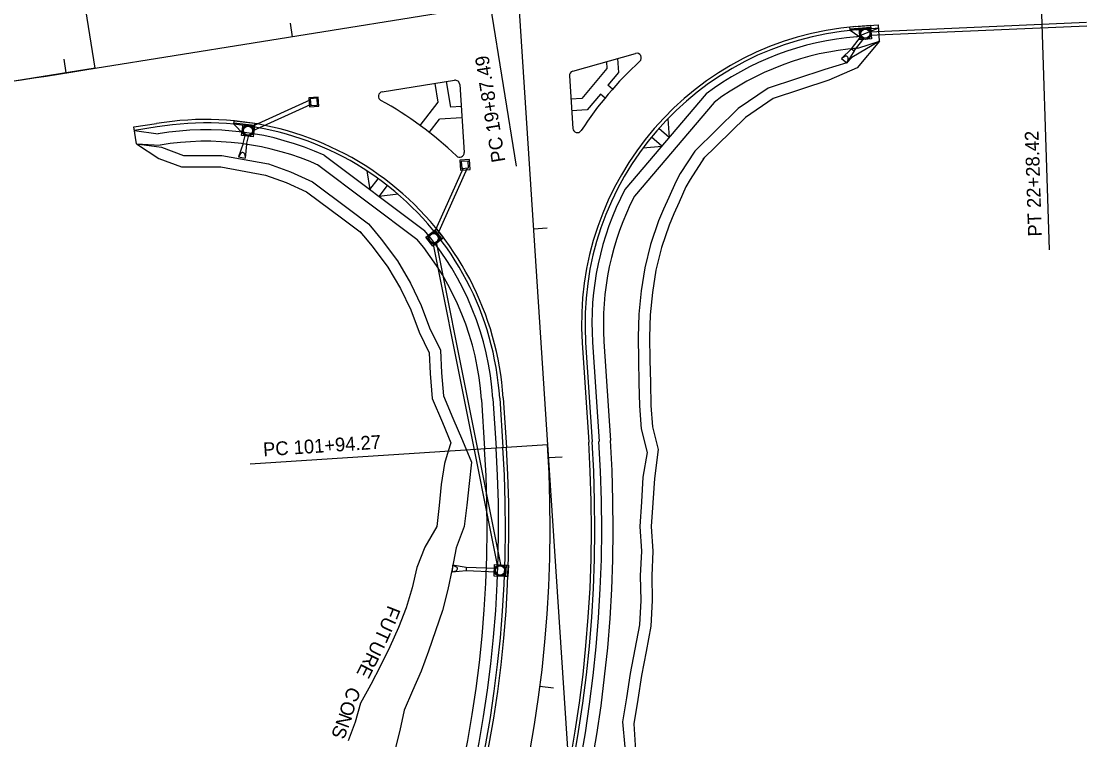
# Model space of a CAD drawing. Extents: x 979959 to 994833, y 1835619 to 1845316.
# Drawn here: x 982435.7 to 982900.6, y 1842333.5 to 1842647 of the extents above; entities that cross this region are included whole.
import ezdxf

# ---------------------------------------------------------------- set-up
doc = ezdxf.new("R2010")
doc.units = 0
for name, color, linetype in [('Future 5 Lane Construction Limits', 7, 'Continuous'), ('R_Drainage', 7, 'Continuous'), ('R_Horz Alg', 7, 'Continuous'), ('R_Horz Alg Annot', 7, 'Continuous'), ('R_Horz Alg Annot_Side Road', 7, 'Continuous'), ('R_Horz Alg Stationing', 7, 'Continuous'), ('R_Horz Alg Stationing_Side Road', 7, 'Continuous'), ('R_Proposed Const Limits', 7, 'Continuous'), ('R_Proposed Road', 7, 'Continuous')]:
    doc.layers.add(name, color=color, linetype=linetype)

msp = doc.modelspace()

# ---------------------------------------------------------------- linework, layer by layer
at = {"layer": 'Future 5 Lane Construction Limits'}
for points in [[(982810.26, 1842638.37), (982800.43, 1842626.73), (982788.12, 1842621.27), (982763.82, 1842613.33), (982751.67, 1842605.09), (982733.13, 1842586.84)], [(982485.98, 1842593.61), (982495.65, 1842587.2), (982505.6, 1842583.46), (982522.74, 1842583.5), (982542.28, 1842579.93), (982551.28, 1842576.73), (982560.22, 1842572.61), (982575.97, 1842560.88), (982584.11, 1842554.66)], [(982733.83, 1842587.7), (982727.56, 1842577.95), (982725.75, 1842574.77), (982722.78, 1842568.13), (982720.46, 1842563.03), (982718.41, 1842558.12), (982715.13, 1842548.23), (982712.66, 1842538.45), (982711.15, 1842528.69), (982710.17, 1842518.91), (982709.88, 1842509.15), (982710.03, 1842499.26), (982710.22, 1842489.28), (982710.47, 1842479.41), (982711.14, 1842469.98), (982713.61, 1842460.1)], [(982583.44, 1842555.27), (982585.09, 1842553.46), (982588.84, 1842548.91), (982595.61, 1842539.65), (982601.13, 1842530.4), (982605.61, 1842521.09), (982609.29, 1842511.28), (982613.73, 1842502.31), (982614.05, 1842493.26), (982614.99, 1842482.38), (982619.43, 1842471.89), (982623.2, 1842463.11)], [(982623.2, 1842463.11), (982622.02, 1842459.42), (982620.34, 1842454.04), (982618.98, 1842444.82), (982618.06, 1842435.67), (982616.99, 1842426.55), (982611.78, 1842417.56), (982608.24, 1842408.68), (982606.24, 1842399.84), (982603.68, 1842391.1), (982600.32, 1842382.5), (982596.45, 1842374.05), (982592.4, 1842365.73), (982588.19, 1842357.54), (982587.38, 1842356.05), (982583.77, 1842349.5), (982581.39, 1842341.2), (982578.38, 1842333.05)], [(982713.61, 1842460.1), (982711.94, 1842447.46), (982711.28, 1842436.93), (982710.57, 1842426.53), (982711.31, 1842415.85), (982710.78, 1842405), (982710.98, 1842394.25), (982710.44, 1842383), (982708.35, 1842372.06), (982706.38, 1842361.59), (982704.77, 1842351.04), (982702.96, 1842340.45)], [(982702.96, 1842340.45), (982704.27, 1842319.44), (982705.92, 1842307.91), (982706.96, 1842296.36), (982707.4, 1842284.83), (982707.25, 1842273.14), (982704.91, 1842261.25), (982696.82, 1842251.43), (982690.14, 1842243.07), (982689.97, 1842232.63)]]:
    msp.add_lwpolyline(points, dxfattribs=at)
at = {"layer": 'R_Drainage'}
for p, q in [((982806.31, 1842644.32), (982797.34, 1842643.65)), ((982805.82, 1842642.47), (982900.54, 1842646.59)), ((982805.89, 1842640.97), (982900.6, 1842645.09)), ((982797.38, 1842643.16), (982802.59, 1842639.58)), ((982797.93, 1842635.07), (982802.27, 1842640.64)), ((982799.12, 1842634.15), (982803.46, 1842639.72)), ((982797.93, 1842635.07), (982793.6, 1842630.74)), ((982797.93, 1842635.07), (982799.12, 1842634.15)), ((982806.68, 1842639.33), (982801.7, 1842638.96)), ((982795.02, 1842631.64), (982793.6, 1842630.74)), ((982793.6, 1842630.74), (982795.97, 1842628.89)), ((982799.12, 1842634.15), (982795.97, 1842628.89)), ((982796.51, 1842630.48), (982795.97, 1842628.89)), ((982535.87, 1842600.89), (982561.81, 1842612.69)), ((982536.63, 1842599.23), (982561.94, 1842610.73)), ((982537.42, 1842601.5), (982528.48, 1842602.6)), ((982528.42, 1842602.1), (982532.84, 1842597.58)), ((982532.49, 1842593.64), (982530.5, 1842587.84)), ((982536.81, 1842596.54), (982531.84, 1842597.15)), ((982532.49, 1842593.64), (982533.96, 1842593.33)), ((982532.5, 1842593.66), (982533.47, 1842597.7)), ((982533.96, 1842593.33), (982533.44, 1842587.22)), ((982533.96, 1842593.31), (982534.93, 1842597.35)), ((982531.38, 1842589.27), (982530.5, 1842587.84)), ((982533.22, 1842588.88), (982533.44, 1842587.22)), ((982530.5, 1842587.84), (982533.44, 1842587.22)), ((982628.55, 1842582.87), (982615.76, 1842554.35)), ((982628.55, 1842582.87), (982615.76, 1842554.35)), ((982630.24, 1842582.98), (982617.13, 1842553.74)), ((982630.24, 1842582.98), (982617.13, 1842553.74)), ((982615.24, 1842548.85), (982612.18, 1842552.8)), ((982615.32, 1842550.39), (982643.54, 1842409.01)), ((982615.32, 1842550.39), (982643.54, 1842409.01)), ((982616.79, 1842550.68), (982645.01, 1842409.3)), ((982616.79, 1842550.68), (982645.01, 1842409.3)), ((982623.81, 1842409.61), (982623.7, 1842406.61)), ((982629.86, 1842408.63), (982623.81, 1842409.61)), ((982625.37, 1842408.99), (982623.81, 1842409.61)), ((982629.86, 1842408.63), (982629.81, 1842407.14)), ((982642.81, 1842408.16), (982629.86, 1842408.63)), ((982642.81, 1842408.16), (982629.86, 1842408.63)), ((982642.05, 1842404.93), (982642.23, 1842409.93)), ((982629.81, 1842407.14), (982623.7, 1842406.61)), ((982625.3, 1842407.1), (982623.7, 1842406.61)), ((982642.76, 1842406.66), (982629.81, 1842407.14)), ((982642.76, 1842406.66), (982629.81, 1842407.14))]:
    msp.add_line(p, q, dxfattribs=at)
for points in [[(982806.35, 1842643.82), (982797.38, 1842643.16), (982797.26, 1842644.65), (982806.24, 1842645.32)], [(982806.68, 1842639.33), (982801.7, 1842638.96), (982801.33, 1842643.95), (982806.31, 1842644.32)], [(982565.24, 1842613.94), (982561.24, 1842613.68), (982561.5, 1842609.68), (982565.5, 1842609.94)], [(982564.77, 1842613.4), (982561.78, 1842613.21), (982561.97, 1842610.22), (982564.96, 1842610.41)], [(982537.36, 1842601), (982528.42, 1842602.1), (982528.61, 1842603.59), (982537.54, 1842602.49)], [(982536.81, 1842596.54), (982531.84, 1842597.15), (982532.45, 1842602.11), (982537.42, 1842601.5)], [(982626.99, 1842586.44), (982627.28, 1842582.12), (982631.6, 1842582.4), (982631.32, 1842586.73)], [(982627.7, 1842585.82), (982627.9, 1842582.83), (982630.89, 1842583.02), (982630.7, 1842586.02)], [(982618.8, 1842551.6), (982615.74, 1842555.56), (982616.93, 1842556.48), (982619.99, 1842552.52)], [(982615.24, 1842548.85), (982612.18, 1842552.8), (982616.13, 1842555.86), (982619.2, 1842551.91)], [(982642.05, 1842404.93), (982642.23, 1842409.93), (982647.23, 1842409.74), (982647.04, 1842404.75)], [(982646.54, 1842404.77), (982646.73, 1842409.76), (982648.23, 1842409.71), (982648.04, 1842404.71)]]:
    msp.add_lwpolyline(points, close=True, dxfattribs=at)
for centre, radius in [((982804.01, 1842641.64), 2.5), ((982804.01, 1842641.64), 2.5), ((982804.01, 1842641.64), 2), ((982804.01, 1842641.64), 2), ((982534.63, 1842599.32), 2.5), ((982534.63, 1842599.32), 2.5), ((982534.63, 1842599.32), 2), ((982534.63, 1842599.32), 2), ((982615.69, 1842552.36), 2.5), ((982615.69, 1842552.36), 2.5), ((982615.69, 1842552.36), 2), ((982615.69, 1842552.36), 2), ((982644.64, 1842407.34), 2.5), ((982644.64, 1842407.34), 2.5), ((982644.64, 1842407.34), 2), ((982644.64, 1842407.34), 2)]:
    msp.add_circle(centre, radius, dxfattribs=at)
for centre, start, end in [((982795.56, 1842630.79), 341.4196, 122.7056), ((982532.23, 1842588.75), 7.3963, 148.6823), ((982625.01, 1842408.06), 287.2412, 68.5271)]:
    msp.add_arc(centre, 1, start, end, dxfattribs=at)
at = {"layer": 'R_Horz Alg'}
for p, q in [((982467.97, 1842626.52), (982640.32, 1842654.16)), ((982652.68, 1842656.1), (982665.33, 1842462.24))]:
    msp.add_line(p, q, dxfattribs=at)
for centre, radius, start, end in [((981863.15, 1846398.05), 3819.72, 276.50701, 279.11059), ((982120.82, 1842426.69), 545.67, 283.2783, 3.7353)]:
    msp.add_arc(centre, radius, start, end, dxfattribs=at)
at = {"layer": 'R_Horz Alg Annot'}
msp.add_lwpolyline([(982665.33, 1842462.24), (982535.61, 1842453.77)], dxfattribs=at)
at = {"layer": 'R_Horz Alg Annot_Side Road'}
for p, q in [((982467.97, 1842626.52), (982382.26, 1842612.78)), ((982665.33, 1842462.24), (982695.41, 1842001.62))]:
    msp.add_line(p, q, dxfattribs=at)
for points in [[(982467.97, 1842626.52), (982447.38, 1842754.88)], [(982879.99, 1842677.22), (982884.26, 1842547.29)], [(982640.32, 1842654.16), (982651.6, 1842583.83)]]:
    msp.add_lwpolyline(points, dxfattribs=at)
at = {"layer": 'R_Horz Alg Stationing'}
for points in [[(982665.18, 1842556.7), (982659.19, 1842556.31)], [(982671.67, 1842456.85), (982665.68, 1842456.52)], [(982667.94, 1842355.96), (982661.99, 1842356.73)]]:
    msp.add_lwpolyline(points, dxfattribs=at)
at = {"layer": 'R_Horz Alg Stationing_Side Road'}
for points in [[(982552.98, 1842646.23), (982553.93, 1842640.31)], [(982454.26, 1842630.42), (982455.19, 1842624.49)]]:
    msp.add_lwpolyline(points, dxfattribs=at)
at = {"layer": 'R_Proposed Const Limits'}
msp.add_line((982698.03, 1842341.29), (982699.07, 1842330.28), dxfattribs=at)
for points in [[(982810.26, 1842638.37), (982798.13, 1842631.18), (982795.97, 1842628.89), (982786.33, 1842625.95), (982761.59, 1842617.86), (982748.49, 1842608.97), (982729.62, 1842590.41)], [(982485.98, 1842593.61), (982496.89, 1842592.08), (982506.5, 1842588.46), (982523.18, 1842588.51), (982543.57, 1842584.78), (982553.17, 1842581.36), (982562.79, 1842576.93), (982578.98, 1842564.87), (982587.14, 1842558.64)], [(982729.62, 1842590.41), (982723.28, 1842580.54), (982721.28, 1842577.03), (982718.22, 1842570.19), (982715.87, 1842565.02), (982713.73, 1842559.87), (982710.32, 1842549.63), (982707.76, 1842539.44), (982706.19, 1842529.32), (982705.18, 1842519.23), (982704.88, 1842509.19), (982705.03, 1842499.18), (982705.22, 1842489.17), (982705.48, 1842479.16), (982706.18, 1842469.19), (982708.76, 1842458.88)], [(982587.14, 1842558.64), (982588.87, 1842556.73), (982592.79, 1842551.98), (982599.79, 1842542.41), (982605.54, 1842532.77), (982610.21, 1842523.05), (982613.89, 1842513.27), (982618.69, 1842503.56), (982619.04, 1842493.56), (982619.9, 1842483.6), (982624.03, 1842473.85), (982628.21, 1842464.1), (982632.21, 1842454.69)], [(982708.76, 1842458.88), (982706.97, 1842448.02), (982706.29, 1842437.26), (982705.55, 1842426.53), (982706.3, 1842415.8), (982705.78, 1842405.08), (982705.98, 1842394.32), (982705.46, 1842383.59), (982703.44, 1842372.99), (982701.45, 1842362.42), (982699.84, 1842351.84), (982698.03, 1842341.29)], [(982632.21, 1842454.69), (982631.18, 1842445.26), (982630.18, 1842435.88), (982628.95, 1842426.55), (982625.47, 1842417.3), (982623.76, 1842408.11), (982621.78, 1842398.98), (982619.57, 1842389.92), (982616.51, 1842381), (982613.34, 1842372.18), (982610.22, 1842363.42), (982606.38, 1842354.85), (982602.75, 1842346.34), (982600.91, 1842337.57), (982598.77, 1842328.88)]]:
    msp.add_lwpolyline(points, dxfattribs=at)
at = {"layer": 'R_Proposed Road'}
for p, q in [((982799.93, 1842644.75), (982809.75, 1842645.53)), ((982810.26, 1842638.37), (982809.75, 1842645.53)), ((982800.05, 1842643.26), (982809.84, 1842644.23)), ((982800.28, 1842640.27), (982809.84, 1842644.23)), ((982800.68, 1842635.28), (982810.26, 1842638.37)), ((982676.32, 1842625.22), (982703.74, 1842632.98)), ((982695.92, 1842630.77), (982696.32, 1842624.68)), ((982691.2, 1842626.36), (982680.23, 1842613.3)), ((982691, 1842629.38), (982691.2, 1842626.36)), ((982593.23, 1842616.23), (982624.7, 1842621.27)), ((982674.87, 1842623.17), (982676.36, 1842600.28)), ((982696.32, 1842624.68), (982691.61, 1842619.08)), ((982617.66, 1842611.73), (982616.34, 1842619.93)), ((982623.07, 1842609.57), (982621.28, 1842620.72)), ((982627.01, 1842619.43), (982628.95, 1842589.81)), ((982693.65, 1842617.35), (982691.61, 1842619.08)), ((982609.69, 1842601.57), (982617.66, 1842611.73)), ((982680.23, 1842613.3), (982675.53, 1842613)), ((982688.39, 1842615.25), (982682.68, 1842608.45)), ((982690.41, 1842613.53), (982688.39, 1842615.25)), ((982734.54, 1842615.29), (982699.1, 1842573.54)), ((982627.64, 1842609.87), (982623.07, 1842609.57)), ((982682.68, 1842608.45), (982675.86, 1842608.01)), ((982738, 1842611.63), (982703.27, 1842570.73)), ((982613.68, 1842598.55), (982618.14, 1842604.24)), ((982627.96, 1842604.88), (982618.14, 1842604.24)), ((982717.78, 1842604.44), (982718.44, 1842596.33)), ((982484.81, 1842600.89), (982494.7, 1842602.37)), ((982485.98, 1842593.61), (982484.81, 1842600.89)), ((982494.95, 1842600.89), (982485.05, 1842599.39)), ((982485.05, 1842599.39), (982495.45, 1842597.93)), ((982718.44, 1842596.33), (982713.87, 1842600.21)), ((982485.98, 1842593.61), (982496.28, 1842593)), ((982715.21, 1842592.51), (982710.63, 1842596.39)), ((982567.88, 1842588.55), (982611.69, 1842555.65)), ((982707.09, 1842591.85), (982715.21, 1842592.51)), ((982564.88, 1842584.55), (982608.24, 1842551.99)), ((982586.54, 1842581.74), (982587.79, 1842573.6)), ((982587.79, 1842573.6), (982591.49, 1842578.33)), ((982591.79, 1842570.6), (982595.49, 1842575.32)), ((982600.12, 1842571.51), (982591.79, 1842570.6)), ((982680.47, 1842506.69), (982683.3, 1842463.41)), ((982681.97, 1842506.79), (982684.79, 1842463.51)), ((982684.96, 1842506.98), (982687.79, 1842463.71)), ((982689.95, 1842507.31), (982692.78, 1842464.03)), ((982636.48, 1842482.02), (982637.89, 1842460.45)), ((982641.47, 1842482.34), (982642.88, 1842460.77)), ((982644.47, 1842482.54), (982645.88, 1842460.97)), ((982645.96, 1842482.64), (982647.37, 1842461.07))]:
    msp.add_line(p, q, dxfattribs=at)
for centre, radius, start, end in [((982810.19, 1842515.16), 130, 94.5301, 183.7353), ((982810.19, 1842515.16), 128.5, 94.5301, 183.7353), ((982810.19, 1842515.16), 125.5, 94.5301, 127.0701), ((982810.19, 1842515.16), 120.5, 94.5301, 126.8102), ((982704.28, 1842631.05), 2, 312.4226, 105.7957), ((982810.19, 1842515.16), 155, 132.4226, 147.1094), ((982625.02, 1842619.3), 2, 3.7353, 99.1106), ((982676.87, 1842623.3), 2, 105.7957, 183.7353), ((982593.55, 1842614.25), 2, 99.1106, 241.1072), ((982516.24, 1842474.17), 158, 46.2164, 61.1072), ((982516.24, 1842474.17), 130, 3.7353, 99.5363), ((982516.24, 1842474.17), 128.5, 3.7353, 99.5363), ((982516.24, 1842474.17), 125.5, 65.7011, 99.5363), ((982678.36, 1842600.42), 2, 183.7353, 327.1094), ((982516.24, 1842474.17), 120.5, 65.7011, 99.5363), ((982626.95, 1842589.68), 2, 226.2164, 3.7353), ((982810.19, 1842515.16), 125.5, 152.2779, 183.7353), ((982810.19, 1842515.16), 120.5, 152.5379, 183.7353), ((982516.24, 1842474.17), 120.5, 3.7353, 40.2282), ((982516.24, 1842474.17), 125.5, 3.7353, 40.4882), ((982120.82, 1842426.69), 563.67, 283.2783, 3.7353), ((982120.82, 1842426.69), 565.17, 283.2783, 3.7353), ((982120.82, 1842426.69), 568.17, 283.2783, 3.7353), ((982120.82, 1842426.69), 573.17, 283.27832, 3.73532), ((982120.82, 1842426.69), 518.17, 283.2783, 3.7353), ((982120.82, 1842426.69), 523.17, 283.2783, 3.7353), ((982120.82, 1842426.69), 526.17, 283.2783, 3.7353), ((982120.82, 1842426.69), 527.67, 283.2783, 3.7353)]:
    msp.add_arc(centre, radius, start, end, dxfattribs=at)

# ---------------------------------------------------------------- texts
at = {"layer": 'Future 5 Lane Construction Limits'}
for s, rotation, p in [('F', 248.6398, (982595.75, 1842392.43)), ('U', 245.4303, (982594.02, 1842387.69)), ('T', 245.4303, (982591.63, 1842382.44)), ('U', 244.0465, (982589.24, 1842377.25)), ('R', 244.0465, (982586.72, 1842372.07)), ('E', 242.7686, (982584.25, 1842367.12)), ('C', 241.1409, (982579.01, 1842357.2)), ('O', 253.9983, (982576.02, 1842350.89)), ('N', 249.7291, (982574.65, 1842345.65)), ('S', 249.7291, (982572.69, 1842340.33))]:
    msp.add_text(s, height=6, rotation=rotation, dxfattribs=at).set_placement(p)
at = {"layer": 'R_Horz Alg Annot'}
for s, rotation, p in [('PC 19+87.49', 99.1106, (982646.98, 1842585.95)), ('PT 22+28.42', 91.8826, (982881.06, 1842553.19)), ('PC 101+94.27', 3.7353, (982541.4, 1842457.16))]:
    msp.add_text(s, height=6, rotation=rotation, dxfattribs=at).set_placement(p)

doc.saveas('drawing.dxf')
